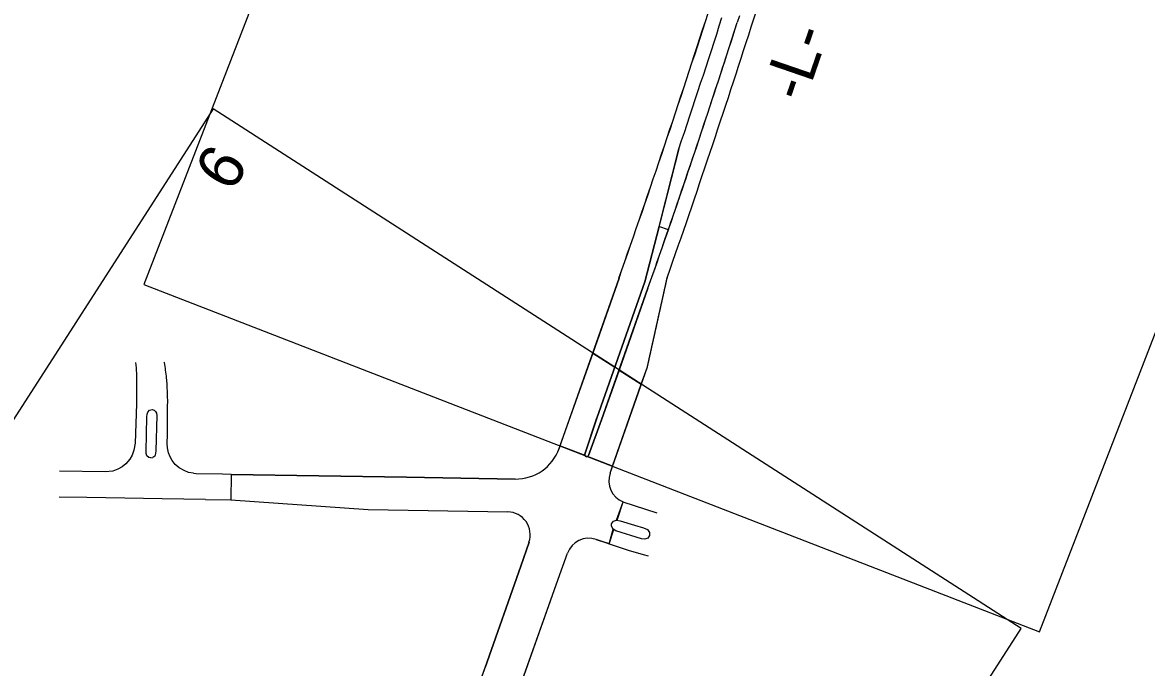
# Model space of a CAD drawing. Extents: x 1970823 to 1988115, y 770601 to 786368.
# Drawn here: x 1976782 to 1978010, y 780658 to 781363 of the extents above; entities that cross this region are included whole.
import ezdxf

# ---------------------------------------------------------------- set-up
doc = ezdxf.new("R2010")
doc.units = 0
for name, color, linetype in [('Old_Level_1', 7, 'Continuous'), ('Old_Level_3', 7, 'Continuous'), ('Prop Conc 5in Monolithic Keyed In Island', 7, 'Continuous'), ('Prop EOT', 7, 'Continuous'), ('Prop Shade Heavy', 7, 'Continuous')]:
    doc.layers.add(name, color=color, linetype=linetype)

msp = doc.modelspace()

# ---------------------------------------------------------------- linework, layer by layer
at = {"layer": 'Old_Level_1'}
for points in [[(1977893.3, 780697.5), (1978399.2, 782002.9), (1977420.1, 782382.3), (1976914.3, 781076.9)], [(1977116.1, 779523.4), (1977873.4, 780700.9), (1976990.2, 781268.9), (1976233, 780091.3)]]:
    msp.add_lwpolyline(points, close=True, dxfattribs=at)
at = {"layer": 'Old_Level_3'}
for p, q in [((1976922.1, 780887.4), (1976924.3, 780887.8)), ((1976968.9, 780870.7), (1976971.8, 780870.3)), ((1977000.3, 780869.7), (1976971.8, 780870.2)), ((1977010, 780869.5), (1977000.3, 780869.7)), ((1976982, 780842.1), (1977009.5, 780841.8)), ((1977425.4, 780812.7), (1977425.6, 780815.6))]:
    msp.add_line(p, q, dxfattribs=at)
for points in [[(1976906.6, 780978.8), (1976906.6, 780948.9), (1976906.5, 780944.9)], [(1976939.6, 780967.3), (1976940.2, 780946.9)], [(1976906.5, 780946.5), (1976904.9, 780903.6), (1976903.7, 780896), (1976901.7, 780890.6), (1976899.2, 780886.1), (1976894.9, 780881.1), (1976890.6, 780877.7), (1976886.2, 780875.2), (1976880.5, 780873.1), (1976872.1, 780872.1), (1976822.1, 780872.9)], [(1976968.9, 780870.7), (1976963.2, 780871.7), (1976958.4, 780873.6), (1976953.2, 780876.7), (1976948.7, 780880.4), (1976945.5, 780884.5), (1976943.2, 780888.6), (1976941.5, 780892.9), (1976940.3, 780898.4), (1976940, 780903.1), (1976940.2, 780913.2), (1976940.2, 780946.6)], [(1976922.1, 780887.4), (1976919.9, 780887.9), (1976917.9, 780889.7), (1976917.1, 780892.2), (1976916.9, 780894.4), (1976917.8, 780932.2), (1976918.1, 780935.2), (1976918.7, 780937.3), (1976920.7, 780939.6), (1976923.4, 780940.4), (1976925.7, 780939.6), (1976927.2, 780938.3), (1976928.3, 780936.3), (1976928.5, 780933.7), (1976927.5, 780895.3), (1976927.3, 780892.3), (1976926.4, 780889.5), (1976924.3, 780887.8)], [(1976982, 780842.1), (1976934.6, 780842.9), (1976893.6, 780843.6), (1976852.3, 780844.2), (1976821.9, 780844.7)], [(1977438.1, 780839.3), (1977475.1, 780827.4)], [(1977425.6, 780815.6), (1977427.6, 780818.3), (1977431.1, 780819.5), (1977434.9, 780818.8), (1977450.8, 780814), (1977460.6, 780810.9), (1977464.8, 780809.2), (1977467, 780805.9), (1977467.1, 780802.6), (1977465.2, 780799.7), (1977462, 780798.5), (1977458.5, 780799.1), (1977430.4, 780807.9), (1977427.3, 780809.6), (1977425.4, 780812.7)], [(1977423, 780793.7), (1977443.8, 780786.8), (1977460.2, 780781.8), (1977465.6, 780780.5)]]:
    msp.add_lwpolyline(points, dxfattribs=at)
for points in [[(1976905.5, 780991.6), (1976906.4, 780980), (1976906.5, 780978.9)], [(1976936.4, 780992.2), (1976936.5, 780991.7), (1976938.9, 780974.6), (1976939.6, 780967.2)]]:
    msp.add_spline(points, degree=3, dxfattribs=at)
at = {"layer": 'Prop Conc 5in Monolithic Keyed In Island'}
for points in [[(1977487.6, 781136.9), (1977486.9, 781137.1), (1977478.2, 781140.1), (1977477.5, 781140.4), (1977461.9, 781079.7), (1977409.6, 780930.9), (1977396.5, 780891.5)], [(1977400.3, 780890.2), (1977414.8, 780929), (1977465.4, 781072.9)]]:
    msp.add_lwpolyline(points, dxfattribs=at)
for centre, radius, start, end in [((1967080, 784724.8), 11008.8, 340.62647, 340.97892), ((1977398.4, 780890.8), 2, 160.3563, 340.9173)]:
    msp.add_arc(centre, radius, start, end, dxfattribs=at)
at = {"layer": 'Prop EOT'}
for p, q in [((1977578.2, 781358.4), (1977609.4, 781455.7)), ((1977499.3, 781225.4), (1977461.9, 781079.7)), ((1977368.3, 780897.8), (1977433.8, 781084)), ((1977409.6, 780930.9), (1977461.9, 781079.7)), ((1977414.8, 780929), (1977465.4, 781072.9)), ((1977424, 780870.9), (1977464.8, 780987)), ((1977396.5, 780891.5), (1977409.7, 780931.1)), ((1977400.3, 780890.2), (1977414.8, 780929)), ((1977010, 780869.5), (1977009.5, 780841.8)), ((1977010, 780869.5), (1977201.4, 780866.4)), ((1977201.4, 780866.4), (1977320.3, 780864.4)), ((1977009.5, 780841.8), (1977159.6, 780831.1)), ((1977159.6, 780831.1), (1977312.1, 780828.5)), ((1977431.6, 780819.4), (1977438.2, 780839.5)), ((1977423, 780793.7), (1977428.2, 780809.1)), ((1977326.5, 780769.3), (1977335.4, 780795.5)), ((1977423, 780793.7), (1977408.8, 780798.4)), ((1977423, 780793.7), (1977420.2, 780794.6)), ((1977367.1, 780755.1), (1977377.4, 780783.3)), ((1977287.5, 780658.4), (1977326.5, 780769.3)), ((1977328.1, 780644.1), (1977367.1, 780755))]:
    msp.add_line(p, q, dxfattribs=at)
for centre, radius, start, end in [((1967080, 784724.8), 10975.2, 340.62647, 342.22085), ((1967080, 784724.8), 11008.8, 340.62647, 342.22085), ((1967080, 784724.8), 10991.2, 341.43473, 342.22085), ((1967080, 784724.8), 11024.8, 340.72417, 342.22085), ((1977321.1, 780914.4), 50, 269.0355, 340.6265), ((1977398.4, 780890.8), 2, 160.3563, 340.9173), ((1977447.6, 780862.6), 25, 160.6265, 247.9083), ((1977311.7, 780803.5), 25, 341.3426, 89.0355), ((1977400.9, 780774.7), 25, 71.6828, 159.9103), ((1975987.1, 781115.7), 1378.5, 320.501, 340.6265)]:
    msp.add_arc(centre, radius, start, end, dxfattribs=at)
for points in [[(1977475.8, 781036.1), (1977475.9, 781036.8), (1977476.1, 781037.5), (1977476.2, 781038.1), (1977476.3, 781038.8), (1977476.5, 781039.5), (1977476.6, 781040.1), (1977476.8, 781040.8), (1977476.9, 781041.5), (1977477.1, 781042.1), (1977477.2, 781042.8), (1977477.4, 781043.5), (1977477.5, 781044.1), (1977477.7, 781044.8), (1977477.8, 781045.5), (1977478, 781046.1), (1977478.1, 781046.8), (1977478.3, 781047.4), (1977478.4, 781048.1), (1977478.6, 781048.8), (1977478.7, 781049.4), (1977478.9, 781050.1), (1977479, 781050.8), (1977479.2, 781051.4), (1977479.3, 781052.1), (1977479.4, 781052.8), (1977479.6, 781053.4), (1977479.7, 781054.1), (1977479.9, 781054.8), (1977480, 781055.4), (1977480.2, 781056.1), (1977480.3, 781056.7), (1977480.5, 781057.4), (1977480.6, 781058.1), (1977480.8, 781058.7), (1977480.9, 781059.4), (1977481.1, 781060.1), (1977481.2, 781060.7), (1977481.4, 781061.4), (1977481.5, 781062.1), (1977481.7, 781062.7), (1977481.8, 781063.4), (1977482, 781064.1), (1977482.1, 781064.7), (1977482.3, 781065.4), (1977482.4, 781066), (1977482.5, 781066.7), (1977482.7, 781067.4), (1977482.8, 781068), (1977483, 781068.7), (1977483.1, 781069.4), (1977483.3, 781070), (1977483.4, 781070.7), (1977483.6, 781071.4), (1977483.7, 781072), (1977483.9, 781072.7), (1977484, 781073.4), (1977484.2, 781074), (1977484.3, 781074.7), (1977484.5, 781075.4), (1977484.6, 781076), (1977484.8, 781076.7), (1977484.9, 781077.4), (1977485.1, 781078), (1977485.2, 781078.7), (1977485.4, 781079.4), (1977485.5, 781080), (1977485.6, 781080.7), (1977485.8, 781081.4), (1977485.9, 781082), (1977486.1, 781082.7), (1977486.2, 781083.4), (1977486.4, 781084), (1977486.7, 781085.4)], [(1977464.8, 780987), (1977465, 780987.7), (1977465.1, 780988.3), (1977465.3, 780989), (1977465.4, 780989.6), (1977465.6, 780990.3), (1977465.7, 780991), (1977465.9, 780991.6), (1977466, 780992.3), (1977466.2, 780993), (1977466.3, 780993.6), (1977466.5, 780994.3), (1977466.6, 780995), (1977466.7, 780995.6), (1977466.9, 780996.3), (1977467, 780997), (1977467.2, 780997.6), (1977467.3, 780998.3), (1977467.5, 780998.9), (1977467.6, 780999.6), (1977467.8, 781000.3), (1977467.9, 781000.9), (1977468.1, 781001.6), (1977468.2, 781002.3), (1977468.4, 781002.9), (1977468.5, 781003.6), (1977468.7, 781004.3), (1977468.8, 781004.9), (1977469, 781005.6), (1977469.1, 781006.3), (1977469.3, 781006.9), (1977469.4, 781007.6), (1977469.6, 781008.2), (1977469.7, 781008.9), (1977469.8, 781009.6), (1977470, 781010.2), (1977470.1, 781010.9), (1977470.3, 781011.6), (1977470.4, 781012.2), (1977470.6, 781012.9), (1977470.7, 781013.6), (1977470.9, 781014.2), (1977471, 781014.9), (1977471.2, 781015.6), (1977471.3, 781016.2), (1977471.5, 781016.9), (1977471.6, 781017.5), (1977471.8, 781018.2), (1977471.9, 781018.9), (1977472.1, 781019.5), (1977472.2, 781020.2), (1977472.4, 781020.9), (1977472.5, 781021.5), (1977472.7, 781022.2), (1977472.8, 781022.9), (1977472.9, 781023.5), (1977473.1, 781024.2), (1977473.2, 781024.9), (1977473.4, 781025.5), (1977473.5, 781026.2), (1977473.7, 781026.8), (1977473.8, 781027.5), (1977474, 781028.2), (1977474.1, 781028.8), (1977474.3, 781029.5), (1977474.4, 781030.2), (1977474.6, 781030.8), (1977474.7, 781031.5), (1977474.9, 781032.2), (1977475, 781032.8), (1977475.2, 781033.5), (1977475.3, 781034.2), (1977475.5, 781034.8), (1977475.6, 781035.5), (1977475.8, 781036.1)]]:
    msp.add_spline(points, degree=3, dxfattribs=at)
at = {"layer": 'Prop Shade Heavy'}
for p, q in [((1977578.2, 781358.4), (1977609.4, 781455.7)), ((1977565.3, 781370.6), (1977563, 781363.3)), ((1977433.8, 781084), (1977405, 781002.1)), ((1977429.2, 780986.6), (1977461.9, 781079.7)), ((1977465.4, 781072.9), (1977433.9, 780983.5)), ((1977405, 781002.1), (1977369.2, 780900.6)), ((1977429.2, 780986.6), (1977405, 781002.1)), ((1977405, 781002.1), (1977429.2, 780986.6)), ((1977433.9, 780983.5), (1977414.8, 780929)), ((1977458.1, 780968), (1977433.9, 780983.5)), ((1977433.9, 780983.5), (1977458.1, 780968)), ((1977458.1, 780968), (1977464.8, 780987)), ((1977426.6, 780878.3), (1977458.1, 780968)), ((1977414.8, 780929), (1977400.3, 780890.2)), ((1977369.2, 780900.6), (1977368.3, 780897.8)), ((1977396.6, 780890), (1977369.2, 780900.6)), ((1977369.2, 780900.6), (1977396.6, 780890)), ((1977426.6, 780878.3), (1977399.2, 780889)), ((1977399.2, 780889), (1977426.6, 780878.3)), ((1977010, 780869.5), (1977009.5, 780841.8)), ((1977201.4, 780866.4), (1977010, 780869.5)), ((1977424, 780870.9), (1977426.6, 780878.3)), ((1977320.3, 780864.4), (1977201.4, 780866.4)), ((1977009.5, 780841.8), (1977159.6, 780831.1)), ((1977159.6, 780831.1), (1977312.1, 780828.5)), ((1977431.1, 780819.5), (1977438.2, 780839.5)), ((1977427.6, 780818.3), (1977431.1, 780819.5)), ((1977427.6, 780818.3), (1977431.1, 780819.5)), ((1977431.1, 780819.5), (1977431.6, 780819.4)), ((1977423, 780793.7), (1977427.3, 780809.6)), ((1977425.4, 780812.7), (1977425.6, 780815.6)), ((1977425.4, 780812.7), (1977425.6, 780815.6)), ((1977427.3, 780809.6), (1977425.4, 780812.7)), ((1977427.3, 780809.6), (1977425.4, 780812.7)), ((1977425.6, 780815.6), (1977427.6, 780818.3)), ((1977425.6, 780815.6), (1977427.6, 780818.3)), ((1977428.2, 780809.1), (1977427.3, 780809.6)), ((1977335.4, 780795.5), (1977326.5, 780769.3)), ((1977408.8, 780798.4), (1977420.2, 780794.6)), ((1977420.2, 780794.6), (1977423, 780793.7)), ((1977367.1, 780755), (1977377.4, 780783.3)), ((1977326.5, 780769.3), (1977287.5, 780658.4)), ((1977328, 780643.9), (1977367.1, 780755))]:
    msp.add_line(p, q, dxfattribs=at)
for points in [[(1977461.9, 781079.7), (1977477.5, 781140.3), (1977499.3, 781225.4)], [(1977396.5, 780891.5), (1977409.6, 780930.9), (1977429.2, 780986.6)], [(1977420.2, 780794.6), (1977420.2, 780794.6)]]:
    msp.add_lwpolyline(points, dxfattribs=at)
for centre, radius, start, end in [((1967080, 784724.8), 10975.3, 340.62647, 342.22085), ((1967080, 784724.8), 11008.8, 340.97892, 342.22085), ((1967080, 784724.8), 10991.2, 341.43473, 342.22085), ((1967080, 784724.8), 11024.8, 340.72417, 342.22085), ((1967080, 784724.8), 11008.8, 340.62647, 340.97892), ((1977321.1, 780914.4), 50, 269.0355, 340.6265), ((1977398.4, 780890.8), 2, 160.3563, 204.5867), ((1977398.4, 780890.8), 2, 204.5867, 293.054), ((1977398.4, 780890.8), 2, 293.054, 340.9173), ((1977447.6, 780862.6), 25, 160.6265, 247.9083), ((1977311.7, 780803.5), 25, 341.3426, 89.0355), ((1977400.9, 780774.7), 25, 71.6828, 159.9103), ((1975987.1, 781115.7), 1378.5, 315.7395, 340.6265)]:
    msp.add_arc(centre, radius, start, end, dxfattribs=at)
for points in [[(1977483, 781069), (1977483.1, 781069.1), (1977483.1, 781069.2), (1977483.1, 781069.4), (1977483.2, 781069.6), (1977483.2, 781069.8), (1977483.3, 781070), (1977483.3, 781070.3), (1977483.4, 781070.5), (1977483.4, 781070.7), (1977483.5, 781070.9), (1977483.5, 781071.1), (1977483.6, 781071.4), (1977483.6, 781071.6), (1977483.7, 781071.8), (1977483.7, 781072), (1977483.8, 781072.3), (1977483.8, 781072.5), (1977483.9, 781072.7), (1977483.9, 781072.9), (1977484, 781073.1), (1977484, 781073.4), (1977484.1, 781073.6), (1977484.1, 781073.8), (1977484.2, 781074), (1977484.2, 781074.3), (1977484.3, 781074.5), (1977484.3, 781074.7), (1977484.4, 781074.9), (1977484.4, 781075.1), (1977484.5, 781075.4), (1977484.5, 781075.6), (1977484.6, 781075.8), (1977484.6, 781076), (1977484.7, 781076.3), (1977484.7, 781076.5), (1977484.8, 781076.7), (1977484.8, 781076.9), (1977484.9, 781077.1), (1977484.9, 781077.4), (1977485, 781077.6), (1977485, 781077.8), (1977485.1, 781078), (1977485.1, 781078.3), (1977485.2, 781078.5), (1977485.2, 781078.7), (1977485.3, 781078.9), (1977485.3, 781079.1), (1977485.4, 781079.4), (1977485.4, 781079.6), (1977485.5, 781079.8), (1977485.5, 781080), (1977485.6, 781080.2), (1977485.6, 781080.5), (1977485.6, 781080.7), (1977485.7, 781080.9), (1977485.7, 781081.1), (1977485.8, 781081.4), (1977485.8, 781081.6), (1977485.9, 781081.8), (1977485.9, 781082), (1977486, 781082.2), (1977486, 781082.5), (1977486.1, 781082.7), (1977486.1, 781082.9), (1977486.2, 781083.1), (1977486.2, 781083.4), (1977486.3, 781083.6), (1977486.3, 781083.8), (1977486.4, 781084), (1977486.5, 781084.5), (1977486.6, 781084.9), (1977486.7, 781085.4)], [(1977479.4, 781052.6), (1977479.4, 781052.6), (1977479.4, 781052.7), (1977479.4, 781052.8), (1977479.5, 781053), (1977479.5, 781053.2), (1977479.6, 781053.4), (1977479.6, 781053.6), (1977479.7, 781053.9), (1977479.7, 781054.1), (1977479.8, 781054.3), (1977479.8, 781054.5), (1977479.9, 781054.8), (1977479.9, 781055), (1977480, 781055.2), (1977480, 781055.4), (1977480.1, 781055.6), (1977480.1, 781055.9), (1977480.2, 781056.1), (1977480.2, 781056.3), (1977480.3, 781056.5), (1977480.3, 781056.7), (1977480.4, 781057), (1977480.4, 781057.2), (1977480.5, 781057.4), (1977480.5, 781057.6), (1977480.6, 781057.9), (1977480.6, 781058.1), (1977480.7, 781058.3), (1977480.7, 781058.5), (1977480.8, 781058.7), (1977480.8, 781059), (1977480.9, 781059.2), (1977480.9, 781059.4), (1977481, 781059.6), (1977481, 781059.8), (1977481.1, 781060.1), (1977481.1, 781060.3), (1977481.2, 781060.5), (1977481.2, 781060.7), (1977481.3, 781061), (1977481.3, 781061.2), (1977481.4, 781061.4), (1977481.4, 781061.6), (1977481.5, 781061.8), (1977481.5, 781062.1), (1977481.6, 781062.3), (1977481.6, 781062.5), (1977481.7, 781062.7), (1977481.7, 781062.9), (1977481.8, 781063.2), (1977481.8, 781063.4), (1977481.9, 781063.6), (1977481.9, 781063.8), (1977482, 781064.1), (1977482, 781064.3), (1977482.1, 781064.5), (1977482.1, 781064.7), (1977482.2, 781064.9), (1977482.2, 781065.2), (1977482.3, 781065.4), (1977482.3, 781065.6), (1977482.3, 781065.8), (1977482.4, 781066), (1977482.4, 781066.3), (1977482.5, 781066.5), (1977482.5, 781066.7), (1977482.6, 781066.9), (1977482.6, 781067.2), (1977482.7, 781067.4), (1977482.7, 781067.6), (1977482.8, 781067.8), (1977482.8, 781068), (1977482.9, 781068.3), (1977482.9, 781068.5), (1977483, 781068.7), (1977483, 781068.8), (1977483, 781068.9), (1977483, 781069)], [(1977475.8, 781036.1), (1977475.8, 781036.4), (1977475.9, 781036.6), (1977475.9, 781036.8), (1977476, 781037), (1977476, 781037.3), (1977476.1, 781037.5), (1977476.1, 781037.7), (1977476.1, 781037.9), (1977476.2, 781038.1), (1977476.2, 781038.4), (1977476.3, 781038.6), (1977476.3, 781038.8), (1977476.4, 781039), (1977476.4, 781039.3), (1977476.5, 781039.5), (1977476.5, 781039.7), (1977476.6, 781039.9), (1977476.6, 781040.1), (1977476.7, 781040.4), (1977476.7, 781040.6), (1977476.8, 781040.8), (1977476.8, 781041), (1977476.9, 781041.2), (1977476.9, 781041.5), (1977477, 781041.7), (1977477, 781041.9), (1977477.1, 781042.1), (1977477.1, 781042.4), (1977477.2, 781042.6), (1977477.2, 781042.8), (1977477.3, 781043), (1977477.3, 781043.2), (1977477.4, 781043.5), (1977477.4, 781043.7), (1977477.5, 781043.9), (1977477.5, 781044.1), (1977477.6, 781044.3), (1977477.6, 781044.6), (1977477.7, 781044.8), (1977477.7, 781045), (1977477.8, 781045.2), (1977477.8, 781045.5), (1977477.9, 781045.7), (1977477.9, 781045.9), (1977478, 781046.1), (1977478, 781046.3), (1977478.1, 781046.6), (1977478.1, 781046.8), (1977478.2, 781047), (1977478.2, 781047.2), (1977478.3, 781047.4), (1977478.3, 781047.7), (1977478.4, 781047.9), (1977478.4, 781048.1), (1977478.5, 781048.3), (1977478.5, 781048.6), (1977478.6, 781048.8), (1977478.6, 781049), (1977478.7, 781049.2), (1977478.7, 781049.4), (1977478.8, 781049.7), (1977478.8, 781049.9), (1977478.9, 781050.1), (1977478.9, 781050.3), (1977479, 781050.5), (1977479, 781050.8), (1977479.1, 781051), (1977479.1, 781051.2), (1977479.2, 781051.4), (1977479.2, 781051.7), (1977479.2, 781051.9), (1977479.3, 781052.1), (1977479.3, 781052.2), (1977479.4, 781052.4), (1977479.4, 781052.6)], [(1977472.1, 781019.8), (1977472.1, 781019.9), (1977472.2, 781020.1), (1977472.2, 781020.2), (1977472.3, 781020.4), (1977472.3, 781020.6), (1977472.4, 781020.9), (1977472.4, 781021.1), (1977472.5, 781021.3), (1977472.5, 781021.5), (1977472.6, 781021.8), (1977472.6, 781022), (1977472.7, 781022.2), (1977472.7, 781022.4), (1977472.8, 781022.6), (1977472.8, 781022.9), (1977472.9, 781023.1), (1977472.9, 781023.3), (1977472.9, 781023.5), (1977473, 781023.7), (1977473, 781024), (1977473.1, 781024.2), (1977473.1, 781024.4), (1977473.2, 781024.6), (1977473.2, 781024.9), (1977473.3, 781025.1), (1977473.3, 781025.3), (1977473.4, 781025.5), (1977473.4, 781025.7), (1977473.5, 781026), (1977473.5, 781026.2), (1977473.6, 781026.4), (1977473.6, 781026.6), (1977473.7, 781026.8), (1977473.7, 781027.1), (1977473.8, 781027.3), (1977473.8, 781027.5), (1977473.9, 781027.7), (1977473.9, 781028), (1977474, 781028.2), (1977474, 781028.4), (1977474.1, 781028.6), (1977474.1, 781028.8), (1977474.2, 781029.1), (1977474.2, 781029.3), (1977474.3, 781029.5), (1977474.3, 781029.7), (1977474.4, 781029.9), (1977474.4, 781030.2), (1977474.5, 781030.4), (1977474.5, 781030.6), (1977474.6, 781030.8), (1977474.6, 781031.1), (1977474.7, 781031.3), (1977474.7, 781031.5), (1977474.8, 781031.7), (1977474.8, 781031.9), (1977474.9, 781032.2), (1977474.9, 781032.4), (1977475, 781032.6), (1977475, 781032.8), (1977475.1, 781033), (1977475.1, 781033.3), (1977475.2, 781033.5), (1977475.2, 781033.7), (1977475.3, 781033.9), (1977475.3, 781034.2), (1977475.4, 781034.4), (1977475.4, 781034.6), (1977475.5, 781034.8), (1977475.5, 781035), (1977475.6, 781035.3), (1977475.6, 781035.5), (1977475.7, 781035.7), (1977475.7, 781035.9), (1977475.8, 781036.1)], [(1977468.5, 781003.4), (1977468.5, 781003.5), (1977468.5, 781003.5), (1977468.5, 781003.6), (1977468.6, 781003.8), (1977468.6, 781004), (1977468.7, 781004.3), (1977468.7, 781004.5), (1977468.8, 781004.7), (1977468.8, 781004.9), (1977468.9, 781005.1), (1977468.9, 781005.4), (1977469, 781005.6), (1977469, 781005.8), (1977469.1, 781006), (1977469.1, 781006.3), (1977469.2, 781006.5), (1977469.2, 781006.7), (1977469.3, 781006.9), (1977469.3, 781007.1), (1977469.4, 781007.4), (1977469.4, 781007.6), (1977469.5, 781007.8), (1977469.5, 781008), (1977469.6, 781008.2), (1977469.6, 781008.5), (1977469.7, 781008.7), (1977469.7, 781008.9), (1977469.8, 781009.1), (1977469.8, 781009.4), (1977469.8, 781009.6), (1977469.9, 781009.8), (1977469.9, 781010), (1977470, 781010.2), (1977470, 781010.5), (1977470.1, 781010.7), (1977470.1, 781010.9), (1977470.2, 781011.1), (1977470.2, 781011.3), (1977470.3, 781011.6), (1977470.3, 781011.8), (1977470.4, 781012), (1977470.4, 781012.2), (1977470.5, 781012.5), (1977470.5, 781012.7), (1977470.6, 781012.9), (1977470.6, 781013.1), (1977470.7, 781013.3), (1977470.7, 781013.6), (1977470.8, 781013.8), (1977470.8, 781014), (1977470.9, 781014.2), (1977470.9, 781014.4), (1977471, 781014.7), (1977471, 781014.9), (1977471.1, 781015.1), (1977471.1, 781015.3), (1977471.2, 781015.6), (1977471.2, 781015.8), (1977471.3, 781016), (1977471.3, 781016.2), (1977471.4, 781016.4), (1977471.4, 781016.7), (1977471.5, 781016.9), (1977471.5, 781017.1), (1977471.6, 781017.3), (1977471.6, 781017.5), (1977471.7, 781017.8), (1977471.7, 781018), (1977471.8, 781018.2), (1977471.8, 781018.4), (1977471.9, 781018.7), (1977471.9, 781018.9), (1977472, 781019.1), (1977472, 781019.3), (1977472.1, 781019.5), (1977472.1, 781019.6), (1977472.1, 781019.7), (1977472.1, 781019.8)], [(1977464.8, 780987), (1977464.9, 780987.2), (1977464.9, 780987.4), (1977465, 780987.7), (1977465, 780987.9), (1977465.1, 780988.1), (1977465.1, 780988.3), (1977465.2, 780988.5), (1977465.2, 780988.8), (1977465.3, 780989), (1977465.3, 780989.2), (1977465.4, 780989.4), (1977465.4, 780989.6), (1977465.5, 780989.9), (1977465.5, 780990.1), (1977465.6, 780990.3), (1977465.6, 780990.5), (1977465.7, 780990.8), (1977465.7, 780991), (1977465.8, 780991.2), (1977465.8, 780991.4), (1977465.9, 780991.6), (1977465.9, 780991.9), (1977466, 780992.1), (1977466, 780992.3), (1977466.1, 780992.5), (1977466.1, 780992.7), (1977466.2, 780993), (1977466.2, 780993.2), (1977466.3, 780993.4), (1977466.3, 780993.6), (1977466.4, 780993.9), (1977466.4, 780994.1), (1977466.5, 780994.3), (1977466.5, 780994.5), (1977466.6, 780994.7), (1977466.6, 780995), (1977466.6, 780995.2), (1977466.7, 780995.4), (1977466.7, 780995.6), (1977466.8, 780995.8), (1977466.8, 780996.1), (1977466.9, 780996.3), (1977466.9, 780996.5), (1977467, 780996.7), (1977467, 780997), (1977467.1, 780997.2), (1977467.1, 780997.4), (1977467.2, 780997.6), (1977467.2, 780997.8), (1977467.3, 780998.1), (1977467.3, 780998.3), (1977467.4, 780998.5), (1977467.4, 780998.7), (1977467.5, 780998.9), (1977467.5, 780999.2), (1977467.6, 780999.4), (1977467.6, 780999.6), (1977467.7, 780999.8), (1977467.7, 781000.1), (1977467.8, 781000.3), (1977467.8, 781000.5), (1977467.9, 781000.7), (1977467.9, 781000.9), (1977468, 781001.2), (1977468, 781001.4), (1977468.1, 781001.6), (1977468.1, 781001.8), (1977468.2, 781002), (1977468.2, 781002.3), (1977468.3, 781002.5), (1977468.3, 781002.7), (1977468.4, 781002.9), (1977468.4, 781003.1), (1977468.4, 781003.2), (1977468.5, 781003.4)]]:
    msp.add_open_spline(points, degree=3, dxfattribs=at)

# ---------------------------------------------------------------- texts
at = {"layer": 'Old_Level_1'}
for s, rotation, p in [('-L-', 71.0193, (1977636.7, 781274.5)), ('6', 58.1857, (1977010.1, 781176.2))]:
    msp.add_text(s, height=50, rotation=rotation, dxfattribs=at).set_placement(p)

doc.saveas('drawing.dxf')
